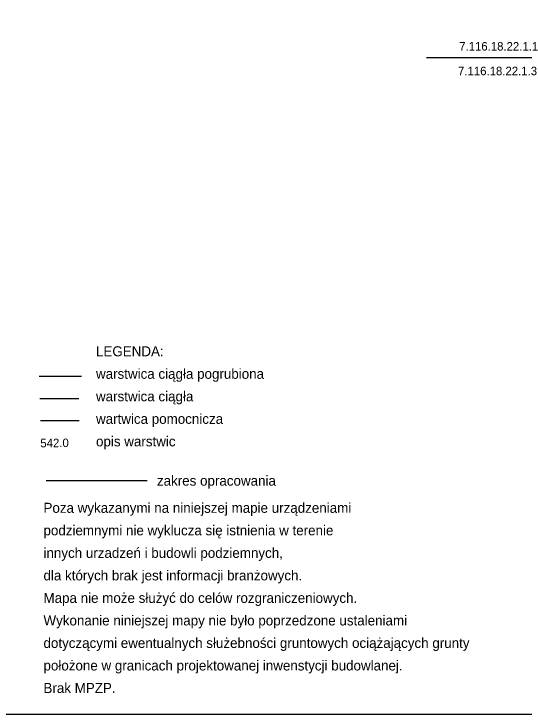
# Model space of a CAD drawing. Extents: x 7477803 to 7478145, y 5500698 to 5500984.
# Drawn here: x 7477904.4 to 7477945.2, y 5500697.6 to 5500753.5 of the extents above; entities that cross this region are included whole.
import ezdxf

# ---------------------------------------------------------------- set-up
doc = ezdxf.new("R2010")
doc.units = 0
for name, color, linetype in [('robocza11', 7, 'Continuous'), ('robocza49', 7, 'Continuous'), ('robocza50', 7, 'Continuous'), ('warst_przeryw', 7, 'Continuous'), ('zakresy', 7, 'Continuous')]:
    doc.layers.add(name, color=color, linetype=linetype)

msp = doc.modelspace()

# ---------------------------------------------------------------- linework, layer by layer
at = {"layer": 'robocza11'}
msp.add_lwpolyline([(7478014.996, 5500697.565), (7478144.729, 5500697.565), (7478144.729, 5500983.565), (7477803.256, 5500983.565), (7477803.256, 5500697.565), (7478010.821, 5500697.565)], close=True, dxfattribs=at)
at = {"layer": 'robocza49'}
msp.add_line((7478000, 5500750), (7477937.375, 5500750), dxfattribs=at)
at = {"layer": 'robocza50'}
for p, q in [((7477906.389, 5500724.557), (7477909.774, 5500724.557)), ((7477906.437, 5500722.787), (7477909.548, 5500722.787))]:
    msp.add_line(p, q, dxfattribs=at)
at = {"layer": 'warst_przeryw'}
msp.add_line((7477906.486, 5500721.018), (7477909.597, 5500721.018), dxfattribs=at)
at = {"layer": 'zakresy'}
msp.add_line((7477906.943, 5500716.239), (7477915.02, 5500716.239), dxfattribs=at)

# ---------------------------------------------------------------- texts
at = {"layer": 'robocza50'}
for s, height, p in [('7.116.18.22.1.1', 0.68, (7477939.978, 5500750.59)), ('7.116.18.22.1.3', 0.68, (7477939.886, 5500748.62)), ('LEGENDA:', 0.8, (7477910.932, 5500726.156)), ('warstwica ciągła pogrubiona', 0.8, (7477910.932, 5500724.356)), ('warstwica ciągła', 0.8, (7477910.932, 5500722.556)), ('wartwica pomocnicza', 0.8, (7477910.932, 5500720.756)), ('opis warstwic', 0.8, (7477910.932, 5500718.956)), ('zakres opracowania', 0.8, (7477915.806, 5500715.813)), ('Poza wykazanymi na niniejszej mapie urządzeniami', 0.8, (7477906.731, 5500713.644)), ('podziemnymi nie wyklucza się istnienia w terenie', 0.8, (7477906.731, 5500711.844)), ('innych urzadzeń i budowli podziemnych,', 0.8, (7477906.731, 5500710.044)), ('dla których brak jest informacji branżowych.', 0.8, (7477906.731, 5500708.244)), ('Mapa nie może służyć do celów rozgraniczeniowych.', 0.8, (7477906.731, 5500706.444)), ('Wykonanie niniejszej mapy nie było poprzedzone ustaleniami ', 0.8, (7477906.731, 5500704.644)), ('dotyczącymi ewentualnych służebności gruntowych ociążających grunty', 0.8, (7477906.731, 5500702.844)), ('położone w granicach projektowanej inwenstycji budowlanej.', 0.8, (7477906.731, 5500701.044)), ('Brak MPZP. ', 0.8, (7477906.731, 5500699.244))]:
    msp.add_text(s, height=height, dxfattribs=at).set_placement(p)
msp.add_text('542.0', height=0.68, rotation=0.6038, dxfattribs=at).set_placement((7477906.482, 5500718.877))

doc.saveas('drawing.dxf')
